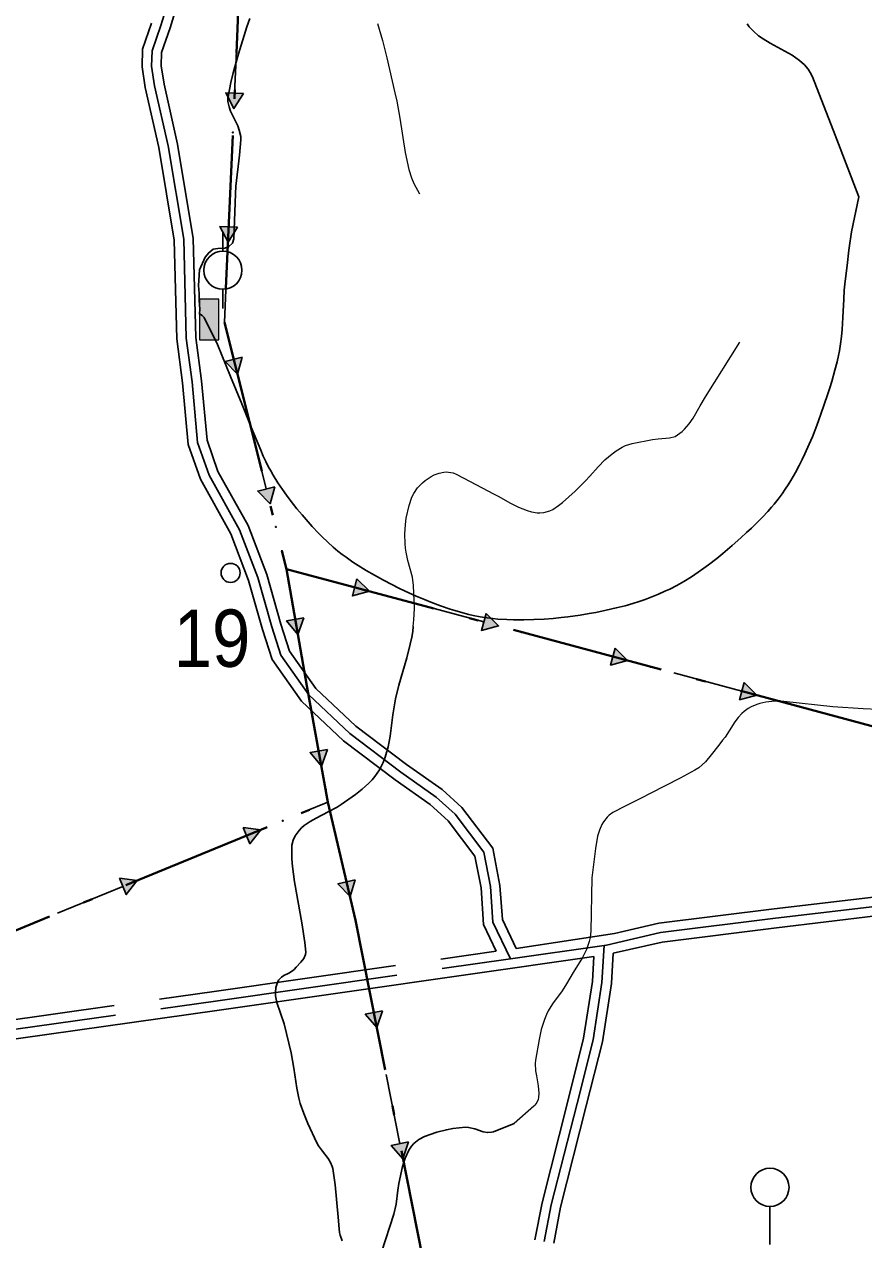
# Model space of a CAD drawing. Extents: x -64005 to -55000, y -89025 to -80000.
# Drawn here: x -62306 to -61427, y -86993 to -85720 of the extents above; entities that cross this region are included whole.
import ezdxf
from ezdxf.enums import TextEntityAlignment as Align

# ---------------------------------------------------------------- set-up
doc = ezdxf.new("R2010")
doc.units = 0
doc.header["$LTSCALE"] = 32
doc.linetypes.add('DOT_DASHED', pattern=[7.7, 5, -1.2, 0.3, -1.2])
doc.linetypes.add('LONG_DASHED', pattern=[7.5, 6, -1.5])
for name, color, linetype, lineweight in [('16', 7, 'Continuous', 25), ('18', 7, 'Continuous', 25), ('2', 7, 'Continuous', 25), ('24', 7, 'Continuous', 25), ('32', 7, 'Continuous', 25), ('39', 7, 'LONG_DASHED', 25), ('52', 7, 'Continuous', 25), ('7', 7, 'Continuous', 13), ('8', 7, 'Continuous', 25)]:
    doc.layers.add(name, color=color, linetype=linetype, lineweight=lineweight)
doc.layers.add('38', color=7, linetype='Continuous')

msp = doc.modelspace()

# ---------------------------------------------------------------- hatches: boundary and pattern name
at = {"layer": '18'}
for points in [[(-62076.34, -85792.59), (-62086.29, -85808.19), (-62094.82, -85791.77)], [(-62082.53, -85932.46), (-62092.48, -85948.05), (-62101.01, -85931.64)], [(-62077.56, -86068.49), (-62082.62, -86086.28), (-62095.5, -86073.01)], [(-62043.4, -86204.26), (-62048.46, -86222.05), (-62061.34, -86208.78)], [(-61957.43, -86300.59), (-61944.35, -86313.68), (-61962.22, -86318.46)], [(-61822.2, -86336.85), (-61809.13, -86349.93), (-61826.99, -86354.72)], [(-62012.91, -86341.5), (-62019.25, -86358.88), (-62031.13, -86344.7)], [(-61686.98, -86373.1), (-61673.9, -86386.19), (-61691.77, -86390.97)], [(-61551.76, -86409.36), (-61538.68, -86422.44), (-61556.55, -86427.23)], [(-61988.38, -86479.29), (-61994.63, -86496.7), (-62006.58, -86482.58)], [(-62076.55, -86560.93), (-62058.22, -86563.4), (-62069.52, -86578.04)], [(-62206.05, -86614.13), (-62187.72, -86616.6), (-62199.02, -86631.24)], [(-61959.29, -86615.7), (-61964.65, -86633.41), (-61977.31, -86619.92)], [(-61930.58, -86753.03), (-61936.53, -86770.55), (-61948.73, -86756.64)], [(-61903.3, -86890.35), (-61909.25, -86907.86), (-61921.45, -86893.95)]]:
    msp.add_hatch(color=256, dxfattribs=at).paths.add_polyline_path(points)
at = {"layer": '7'}
msp.add_hatch(color=256, dxfattribs=at).paths.add_polyline_path([(-62102.24, -86050.25), (-62102.24, -86007.75), (-62122.24, -86007.75), (-62122.24, -86050.25)])

# ---------------------------------------------------------------- linework, layer by layer
at = {"layer": '16'}
for p, q in [((-62097.86, -85957.48), (-62097.87, -85937.48)), ((-62097.85, -86017.48), (-62097.86, -85997.48))]:
    msp.add_line(p, q, dxfattribs=at)
msp.add_circle((-62097.86, -85977.49), 20, dxfattribs=at)
at = {"layer": '18'}
for p, q in [((-62082.3, -85718.28), (-62085.58, -85792.18)), ((-62088.5, -85858.14), (-62091.77, -85932.05)), ((-62070.42, -86134.77), (-62052.37, -86206.52)), ((-62031.28, -86290.37), (-61959.82, -86309.53)), ((-61896.06, -86326.63), (-61824.6, -86345.78)), ((-61760.83, -86362.88), (-61689.38, -86382.04)), ((-61625.61, -86399.14), (-61554.15, -86418.29)), ((-61490.38, -86435.39), (-61418.93, -86454.55)), ((-62011.97, -86544.4), (-61987.81, -86534.48)), ((-61985.16, -86545.78), (-61968.3, -86617.81)), ((-62141.47, -86597.6), (-62073.03, -86569.49)), ((-62270.97, -86650.79), (-62202.53, -86622.68)), ((-61954.07, -86682.27), (-61939.66, -86754.83)), ((-61926.79, -86819.59), (-61912.38, -86892.15))]:
    msp.add_line(p, q, dxfattribs=at)
at = {"layer": '18', "linetype": 'DOT_DASHED', "lineweight": 40}
for points in [[(-61690.71, -84709.91), (-61722.23, -84796.2), (-61746.39, -84828.12), (-62010.45, -85176.95), (-62065.73, -85344.1), (-62096.21, -86032.25), (-62031.28, -86290.37), (-62009.8, -86412.7), (-61987.81, -86534.48), (-61958.9, -86657.97), (-61888.4, -87012.83), (-61934.91, -87241.52), (-61961, -87372.97), (-61973.88, -87489.05)], [(-62031.28, -86290.37), (-61300.5, -86486.3), (-61179.73, -86532.12), (-61069.18, -86626.02), (-60966.6, -86696.29), (-60858.8, -86771.78), (-60980.4, -86988.93), (-61117.47, -87235.6), (-61208.88, -87325.91), (-61262.1, -87419.12), (-61406.49, -87469.74), (-61549.57, -87520.74), (-61667.76, -87630.06), (-61733.17, -87743.6), (-61632.21, -87825.64), (-61575.32, -87886.11)], [(-64000, -87327.84), (-63934.19, -87335.68), (-63775.91, -87352.69), (-63696.16, -87339.73), (-63513.74, -87307.46), (-63108.5, -86909.06), (-62559.52, -86832.54), (-62427.35, -86715.03), (-61987.81, -86534.48)]]:
    msp.add_lwpolyline(points, dxfattribs=at)
at = {"layer": '18'}
for points in [[(-62076.34, -85792.59), (-62086.29, -85808.19), (-62094.82, -85791.77)], [(-62082.53, -85932.46), (-62092.48, -85948.05), (-62101.01, -85931.64)], [(-62077.56, -86068.49), (-62082.62, -86086.28), (-62095.5, -86073.01)], [(-62043.4, -86204.26), (-62048.46, -86222.05), (-62061.34, -86208.78)], [(-61957.43, -86300.59), (-61944.35, -86313.68), (-61962.22, -86318.46)], [(-61822.2, -86336.85), (-61809.13, -86349.93), (-61826.99, -86354.72)], [(-62012.91, -86341.5), (-62019.25, -86358.88), (-62031.13, -86344.7)], [(-61686.98, -86373.1), (-61673.9, -86386.19), (-61691.77, -86390.97)], [(-61551.76, -86409.36), (-61538.68, -86422.44), (-61556.55, -86427.23)], [(-61988.38, -86479.29), (-61994.63, -86496.7), (-62006.58, -86482.58)], [(-62076.55, -86560.93), (-62058.22, -86563.4), (-62069.52, -86578.04)], [(-62206.05, -86614.13), (-62187.72, -86616.6), (-62199.02, -86631.24)], [(-61959.29, -86615.7), (-61964.65, -86633.41), (-61977.31, -86619.92)], [(-61930.58, -86753.03), (-61936.53, -86770.55), (-61948.73, -86756.64)], [(-61903.3, -86890.35), (-61909.25, -86907.86), (-61921.45, -86893.95)]]:
    msp.add_lwpolyline(points, close=True, dxfattribs=at)
for points in [[(-62094.69, -85998), (-62096.21, -86032.25), (-62086.53, -86070.75)], [(-62036.27, -86270.54), (-62031.28, -86290.37), (-62022.02, -86343.1)], [(-62010.6, -86408.13), (-62009.8, -86412.7), (-61997.48, -86480.93)], [(-61899.51, -86956.9), (-61888.4, -87012.83), (-61891.78, -87029.45)]]:
    msp.add_lwpolyline(points, dxfattribs=at)
for centre in [(-62087.39, -85833.16), (-62093.59, -85973.02), (-62076.52, -86110.53), (-62042.36, -86246.3), (-61920.2, -86320.15), (-61784.98, -86356.4), (-62014.93, -86383.5), (-61649.76, -86392.66), (-61514.53, -86428.91), (-61990.19, -86521.3), (-62035.09, -86553.9), (-62164.59, -86607.1), (-62294.09, -86660.29), (-61958.95, -86657.75), (-61931.66, -86795.07), (-61904.38, -86932.38)]:
    msp.add_circle(centre, 0.5, dxfattribs=at)
at = {"layer": '2', "lineweight": 13}
for points in [[(-61935.84, -85719.07), (-61930.64, -85737.08), (-61926.06, -85755.25), (-61917.61, -85791.76), (-61915.72, -85800.6), (-61912.65, -85818.43), (-61907, -85854.21), (-61903.04, -85871.91), (-61900.13, -85880.81), (-61897.68, -85886.56), (-61891.79, -85897.58)], [(-61898.46, -86350.71), (-61897.71, -86343.66), (-61897.25, -86331.55), (-61897.31, -86323.47), (-61898.11, -86307.49), (-61899.4, -86298.8), (-61904, -86281.53), (-61906, -86272.89), (-61906.64, -86268.56), (-61907.07, -86263.67), (-61907.27, -86253.78), (-61906.61, -86243.82), (-61905.71, -86237.17), (-61902.85, -86223.93), (-61899.8, -86215.19), (-61897.76, -86211.14), (-61893.9, -86205.42), (-61888.92, -86200.09), (-61885.95, -86197.55), (-61879.73, -86193.38), (-61876.46, -86191.73), (-61871.45, -86189.9), (-61866.41, -86188.9), (-61863.92, -86188.74), (-61859.05, -86189.15), (-61856.7, -86189.75), (-61853.33, -86191.15), (-61838.72, -86198.85), (-61814.42, -86211.61), (-61808.89, -86214.61), (-61797.22, -86221.06), (-61788.15, -86225.6), (-61779.04, -86229.22), (-61774.53, -86230.51), (-61768.63, -86231.5), (-61765.75, -86231.64), (-61761.51, -86231.34), (-61755.44, -86229.6), (-61752.27, -86228.01), (-61746.17, -86223.95), (-61742.25, -86220.77), (-61728.9, -86208.71), (-61718.1, -86198.15), (-61713.57, -86193.19), (-61704.59, -86183.26), (-61697.59, -86176.13), (-61690.05, -86169.59), (-61685.98, -86166.64), (-61679.42, -86162.71), (-61676.08, -86161.15), (-61669.2, -86158.85), (-61647.96, -86154.7), (-61642.01, -86153.94), (-61629.95, -86153.18), (-61624.19, -86151.51), (-61621.46, -86150), (-61616.87, -86146.48), (-61614.14, -86143.91), (-61609.33, -86138.31), (-61605.19, -86132.26), (-61597.93, -86119.46), (-61592.41, -86109.92), (-61556.39, -86052.93)], [(-61411.34, -86437.43), (-61427.19, -86436.94), (-61458.88, -86434.7), (-61510.1, -86429.21), (-61518.59, -86428.88), (-61522.85, -86429.02), (-61529.2, -86429.71), (-61535.47, -86431.11), (-61538.56, -86432.11), (-61544.6, -86434.79), (-61547.55, -86436.51), (-61551.85, -86439.59), (-61554.19, -86441.62), (-61558.23, -86445.91), (-61561.62, -86450.41), (-61567.4, -86459.69), (-61571.85, -86466.51), (-61574.41, -86469.75), (-61578.41, -86474.7), (-61586.18, -86484.98), (-61592.37, -86492.3), (-61599.39, -86498.59), (-61603.37, -86501.16), (-61618.93, -86509.55), (-61650.31, -86525.55), (-61658.97, -86529.92), (-61676.35, -86538.54), (-61689.33, -86545.36), (-61693.14, -86547.98), (-61695.38, -86550.1), (-61699.16, -86555.04), (-61700.74, -86557.81), (-61703.33, -86563.78), (-61705.27, -86570.12), (-61707.62, -86582.86), (-61711.48, -86613.61), (-61712.43, -86669.64), (-61713.07, -86676.28), (-61714.03, -86680.58), (-61717.01, -86688.96), (-61721.07, -86697.1), (-61730.84, -86712.93), (-61738.03, -86724.73), (-61742.57, -86731.97), (-61752.47, -86745.83), (-61756.95, -86753.13), (-61758.89, -86757.02), (-61761, -86762.13), (-61764.27, -86772.55), (-61766.62, -86783.15), (-61770.26, -86804.51), (-61770.64, -86808.12), (-61770.24, -86815.78), (-61769.43, -86821.06), (-61767.57, -86831.63), (-61766.9, -86839.15), (-61767.25, -86843.79), (-61767.75, -86845.96), (-61768.99, -86848.99), (-61770.91, -86851.72), (-61772.15, -86852.95), (-61792.64, -86871.07)]]:
    msp.add_lwpolyline(points, dxfattribs=at)
at = {"layer": '2'}
for points in [[(-61972.99, -86993.77), (-61975.01, -86988), (-61975.69, -86985), (-61976.18, -86981.46), (-61977.02, -86968.99), (-61980.23, -86935.1), (-61982.69, -86918.22), (-61983.24, -86915.95), (-61985.02, -86911.69), (-61987.49, -86907.7), (-61993.39, -86900.1), (-61997.58, -86894.26), (-61999.28, -86891.16), (-62008.82, -86870.91), (-62013.15, -86860.59), (-62016.78, -86850.03), (-62018.24, -86844.63), (-62020.38, -86834.12), (-62023.49, -86812.93), (-62026.29, -86797.14), (-62033.78, -86766.62), (-62041.36, -86744.31), (-62042.69, -86737.48), (-62042.83, -86733.94), (-62042.28, -86728.64), (-62040.69, -86723.49), (-62039.46, -86721.04), (-62036.53, -86717.72), (-62034.09, -86716.11), (-62028.76, -86713.45), (-62024.98, -86711.14), (-62023.35, -86709.64), (-62020.99, -86707.2), (-62016.05, -86702.22), (-62012.97, -86698.25), (-62011.21, -86693.93), (-62011.04, -86691.6), (-62011.96, -86681.32), (-62015.3, -86660.73), (-62022.88, -86618), (-62024.98, -86602.01), (-62025.55, -86593.95), (-62025.73, -86581.91), (-62025.54, -86579.4), (-62024.38, -86574.46), (-62022.26, -86569.75), (-62018.12, -86564.03), (-62015.54, -86561.5), (-62012.6, -86559.06), (-62006.54, -86554.81), (-62000.29, -86551.19), (-61987.62, -86544.77), (-61978.31, -86539.71), (-61973.83, -86536.79), (-61958.98, -86526.35), (-61951.79, -86520.77), (-61944.9, -86514.56), (-61941.6, -86511.14), (-61938.71, -86507.75), (-61933.77, -86500.55), (-61929.87, -86492.88), (-61927.77, -86487.56), (-61924.65, -86476.54), (-61922.61, -86465.37), (-61919.79, -86442.89), (-61917.06, -86426.21), (-61913.51, -86411.85), (-61905.26, -86383.29), (-61901.54, -86368.9), (-61900, -86361.63), (-61898.99, -86355.68), (-61898.46, -86350.71)], [(-61931.7, -87005.84), (-61918.72, -86966.06), (-61916.44, -86955.43), (-61914.65, -86940.97), (-61913.5, -86933.77), (-61909.81, -86916.01), (-61907.05, -86907.37), (-61902.95, -86898.94), (-61900.23, -86894.82), (-61897.91, -86892.04), (-61892.63, -86887.67), (-61886.69, -86884.52), (-61873.69, -86880.1), (-61863.74, -86877.49), (-61857.1, -86876.25), (-61843.82, -86874.88), (-61840.54, -86875.04), (-61833.91, -86876.7), (-61825.08, -86879.62), (-61820.74, -86880.43), (-61816.51, -86880.23), (-61814.44, -86879.62), (-61792.64, -86871.07)]]:
    msp.add_lwpolyline(points, dxfattribs=at)
at = {"layer": '24'}
for points in [[(-62069.63, -85713.93), (-62072.82, -85722.69), (-62081.63, -85751.02), (-62087.1, -85770.88), (-62089.46, -85780.84), (-62092.55, -85797.43), (-62092.52, -85800.8), (-62091.41, -85806.37), (-62089.8, -85810.82), (-62082.38, -85826.36), (-62080.64, -85830.84), (-62079.16, -85837.64), (-62079.12, -85841.07), (-62080.62, -85857.17), (-62084.16, -85889.56), (-62084.71, -85897.38), (-62086.33, -85944.46), (-62087.92, -85949.11), (-62091.59, -85952.53), (-62095.75, -85954.25), (-62103.08, -85954.73), (-62107.97, -85955.47), (-62112.61, -85959.14), (-62116.28, -85963.78), (-62122.51, -85977.18), (-62123.37, -85993.38), (-62122.63, -86001.94), (-62122.63, -86009.03), (-62122.14, -86018.32), (-62122.39, -86023.21), (-62119.7, -86024.93), (-62117.52, -86026.84), (-62103.67, -86055.17), (-62089.79, -86088.64), (-62078.18, -86117.51)], [(-61442.08, -85956.46), (-61441.86, -85954.05), (-61439.33, -85937.32), (-61431.78, -85900.79), (-61456.34, -85835.94), (-61480.26, -85774.85), (-61482.53, -85770.28), (-61484.73, -85766.94), (-61488.63, -85762.42), (-61493.65, -85757.95), (-61501.63, -85752.43), (-61524.47, -85739.77), (-61531.93, -85735.22), (-61536.62, -85731.89), (-61542.04, -85727.28), (-61546.38, -85722.59), (-61548.7, -85719.61)], [(-61655.61, -86322.26), (-61650.41, -86320.35), (-61641.41, -86316.71), (-61634.74, -86313.74), (-61629.78, -86311.36), (-61622.4, -86307.55), (-61615.1, -86303.42), (-61606.92, -86298.39), (-61599.99, -86293.8), (-61594.09, -86289.65), (-61589.02, -86285.93), (-61580.35, -86279.2), (-61573.96, -86273.99), (-61564.51, -86265.92), (-61555.12, -86257.59), (-61549.23, -86252.24), (-61544.17, -86247.53), (-61539.82, -86243.38), (-61532.42, -86235.96), (-61527.05, -86230.21), (-61523.15, -86225.77), (-61520.29, -86222.36), (-61516.11, -86217.08), (-61512.09, -86211.6), (-61508.74, -86206.7), (-61505.72, -86202.08), (-61502.99, -86197.7), (-61498.14, -86189.41), (-61494.16, -86182.05), (-61490.86, -86175.54), (-61488.09, -86169.79), (-61483.52, -86159.6), (-61480.29, -86151.85), (-61475.69, -86140.07), (-61471.36, -86128.1), (-61464.46, -86108.04), (-61462.01, -86100.5), (-61459.97, -86093.9), (-61456.67, -86082.29), (-61454.48, -86073.54), (-61453.03, -86066.93), (-61452.06, -86061.96), (-61450.82, -86054.45), (-61449.84, -86046.88), (-61449.17, -86039.63), (-61448.38, -86026.92), (-61447.49, -86007.84), (-61446.87, -85998.32), (-61445.94, -85988.82), (-61444.01, -85972.64), (-61442.08, -85956.46)], [(-62078.18, -86117.51), (-62068.18, -86141.77), (-62058.18, -86166.02), (-62055.56, -86172.09), (-62052.93, -86177.69), (-62050.31, -86182.85), (-62047.73, -86187.62), (-62045.21, -86192.04), (-62040.22, -86200.17), (-62035.58, -86207.14), (-62031.33, -86213.14), (-62027.48, -86218.32), (-62020.45, -86227.21), (-62014.96, -86233.77), (-62010.73, -86238.63), (-62004.22, -86245.83), (-61997.53, -86252.93), (-61994.25, -86256.28), (-61987.97, -86262.31), (-61982.34, -86267.32), (-61977.31, -86271.52), (-61972.83, -86275.06), (-61968.84, -86278.06), (-61961.72, -86283.11), (-61956.25, -86286.74), (-61947.83, -86291.97), (-61939.17, -86296.95), (-61929.48, -86302.21), (-61920.98, -86306.61), (-61913.52, -86310.32), (-61906.96, -86313.45), (-61895.39, -86318.66), (-61886.61, -86322.36), (-61879.97, -86325.01), (-61869.87, -86328.78), (-61859.61, -86332.32), (-61854.85, -86333.84), (-61846.52, -86336.25), (-61840.24, -86337.85), (-61835.51, -86338.92), (-61828.36, -86340.32), (-61821.14, -86341.45), (-61815.04, -86342.2), (-61809.69, -86342.73), (-61800.33, -86343.37), (-61793.29, -86343.62), (-61782.75, -86343.69), (-61772.24, -86343.4), (-61761.38, -86342.8), (-61751.9, -86342.05), (-61743.61, -86341.23), (-61736.37, -86340.38), (-61723.72, -86338.61), (-61714.24, -86337.05), (-61707.14, -86335.74), (-61696.49, -86333.57), (-61685.84, -86331.15), (-61676.55, -86328.79), (-61668.53, -86326.5), (-61661.61, -86324.32), (-61655.61, -86322.26)]]:
    msp.add_lwpolyline(points, dxfattribs=at)
at = {"layer": '32'}
msp.add_line((-61524.76, -86957.85), (-61524.76, -86997.85), dxfattribs=at)
msp.add_circle((-61524.76, -86937.85), 20, dxfattribs=at)
at = {"layer": '39'}
for p, q in [((-61796.63, -86698.55), (-61698.37, -86684.5)), ((-61698.37, -86684.5), (-61696.07, -86684.17))]:
    msp.add_line(p, q, dxfattribs=at)
for points in [[(-61796.63, -86698.55), (-61814.94, -86660.06), (-61817.53, -86622.99), (-61824.42, -86586.77), (-61854.59, -86547.12), (-61874.45, -86529.18), (-61911.46, -86503.15), (-61964.91, -86462.63), (-62008, -86422.12), (-62037.3, -86380.73), (-62046.74, -86350.91), (-62061.39, -86299.18), (-62080.35, -86249.17), (-62112.24, -86192.27), (-62124.31, -86157.77), (-62130.22, -86094.28), (-62136.25, -86048.58), (-62138.84, -85945.11), (-62155.1, -85847.2), (-62169.37, -85784.43), (-62172.5, -85763.93), (-62172.09, -85747.83), (-62162.85, -85721.31), (-62155.96, -85698.89)], [(-61696.07, -86684.17), (-61639.32, -86671.13), (-61518.98, -86656.07), (-61415.05, -86643.74), (-61328.91, -86630.05), (-61285.89, -86606.43), (-61228.48, -86567.64), (-61188.06, -86526.11), (-61171.26, -86506.62)], [(-61698.37, -86684.5), (-61700.77, -86723.41), (-61710.13, -86783.54), (-61726.86, -86850.2), (-61753.8, -86956.28), (-61761.18, -86994.57)], [(-62461.36, -86792.73), (-62400.43, -86784.16), (-62105.63, -86742.73), (-61796.63, -86698.55)]]:
    msp.add_lwpolyline(points, dxfattribs=at)
at = {"layer": '52'}
msp.add_circle((-62089.79, -86294.43), 10, dxfattribs=at)
at = {"layer": '7'}
msp.add_lwpolyline([(-62102.24, -86050.25), (-62102.24, -86007.75), (-62122.24, -86007.75), (-62122.24, -86050.25)], close=True, dxfattribs=at)
at = {"layer": '8', "linetype": 'LONG_DASHED'}
msp.add_line((-61790.76, -86687.62), (-61687.76, -86671.99), dxfattribs=at)
at = {"layer": '8'}
for points in [[(-62146.83, -85703.22), (-62153.15, -85723.79), (-62162.13, -85749.56), (-62162.48, -85763.3), (-62159.54, -85782.55), (-62145.24, -85845.56), (-62128.86, -85944.16), (-62126.27, -86047.8), (-62120.28, -86093.16), (-62114.47, -86155.62), (-62103.09, -86188.13), (-62071.26, -86244.92), (-62051.89, -86296.03), (-62037.16, -86348.04), (-62028.24, -86376.23), (-62000.42, -86415.52), (-61958.45, -86454.98), (-61905.38, -86495.21), (-61868.2, -86521.35), (-61847.43, -86540.01), (-61815.04, -86582.59), (-61807.6, -86621.69), (-61805.1, -86657.47), (-61790.76, -86687.62)], [(-61688.86, -86692.78), (-61637.58, -86680.99), (-61517.77, -86666), (-61413.68, -86653.65), (-61325.48, -86639.63), (-61280.67, -86614.97), (-61222.03, -86575.35), (-61180.87, -86533.09), (-61170.2, -86520.53)], [(-61688.86, -86692.78), (-61690.82, -86724.49), (-61700.32, -86785.53), (-61717.16, -86852.65), (-61744.04, -86958.46), (-61751.34, -86996.34)], [(-63072.02, -86888.02), (-62870.97, -86860.44), (-62399.04, -86794.06), (-62104.23, -86752.63), (-61709.1, -86696.15)]]:
    msp.add_lwpolyline(points, dxfattribs=at)
at = {"layer": '8', "linetype": 'LONG_DASHED'}
for points in [[(-62172.55, -85718.83), (-62182.05, -85746.1), (-62182.52, -85764.57), (-62179.2, -85786.3), (-62164.96, -85848.84), (-62148.82, -85946.06), (-62146.23, -86049.36), (-62140.16, -86095.4), (-62134.15, -86159.93), (-62121.39, -86196.4), (-62089.44, -86253.41), (-62070.89, -86302.32), (-62056.32, -86353.78), (-62046.36, -86385.23), (-62015.58, -86428.72), (-61971.37, -86470.29), (-61917.54, -86511.09), (-61880.7, -86537.01), (-61861.75, -86554.22), (-61833.8, -86590.96), (-61827.46, -86624.28), (-61824.78, -86662.65), (-61811.5, -86690.58)], [(-61687.76, -86671.99), (-61641.06, -86661.26), (-61520.19, -86646.14), (-61416.42, -86633.83), (-61332.34, -86620.48), (-61291.11, -86597.89), (-61234.93, -86559.93), (-61195.25, -86519.13), (-61183.64, -86505.45)], [(-62428.99, -86778.08), (-62401.82, -86774.26), (-62107.03, -86732.83), (-61811.5, -86690.58)], [(-61709.1, -86696.15), (-61710.72, -86722.33), (-61719.94, -86781.55), (-61736.56, -86847.75), (-61763.56, -86954.1), (-61771.02, -86992.8)]]:
    msp.add_lwpolyline(points, dxfattribs=at)

# ---------------------------------------------------------------- texts
at = {"layer": '38', "width": 0.9}
msp.add_text('19', height=60, rotation=0.008, dxfattribs=at).set_placement((-62109.26, -86392.81), align=Align.CENTER)

doc.saveas('drawing.dxf')
